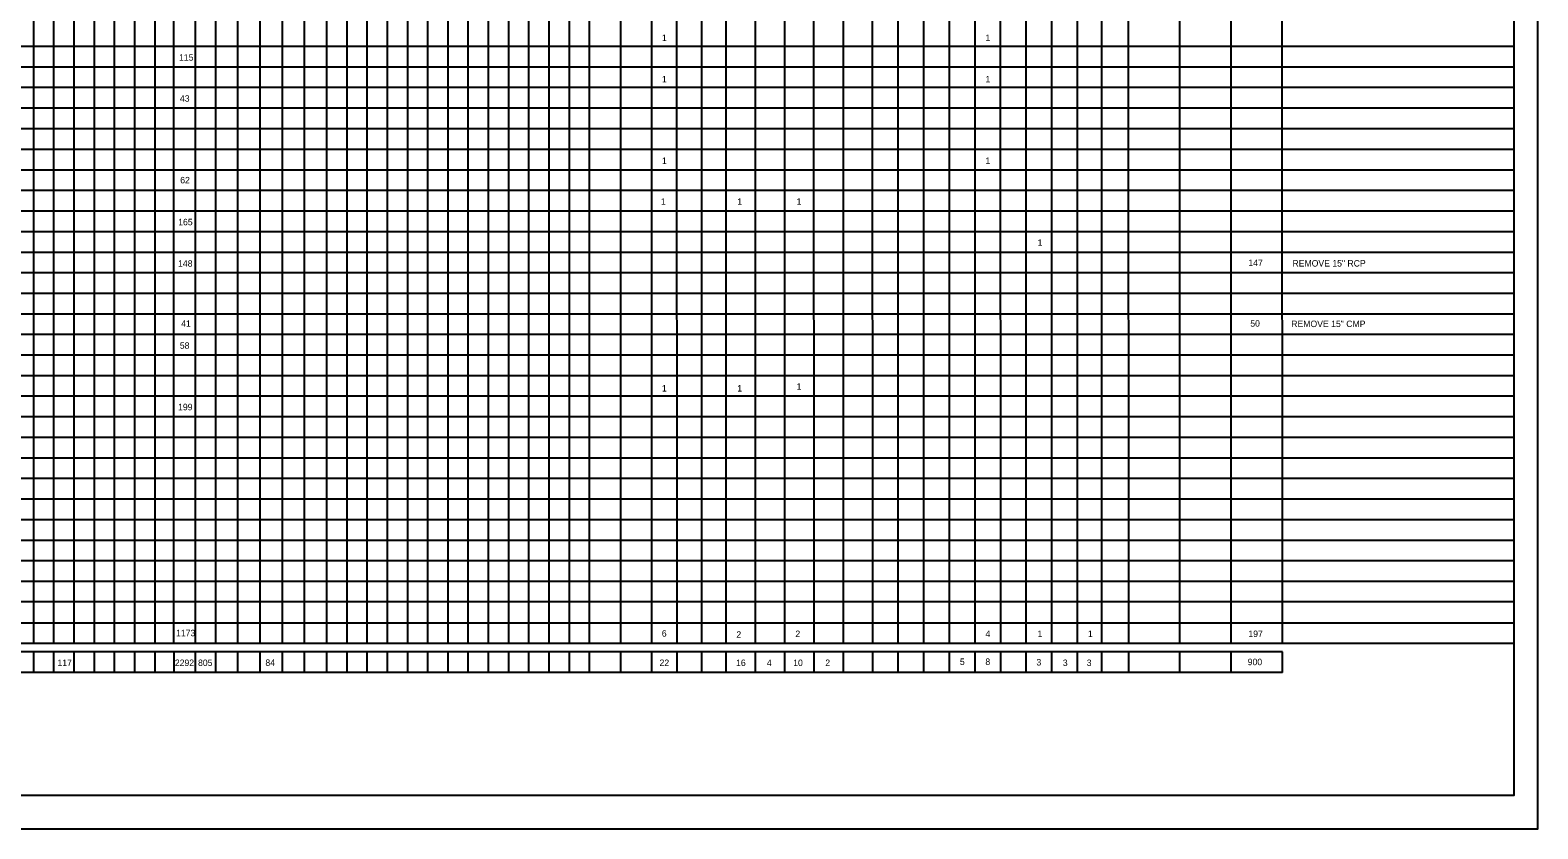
# Model space of a CAD drawing. Extents: x 809447 to 814738, y 647528 to 651206.
# Drawn here: x 813593 to 814712, y 650017 to 650609 of the extents above; entities that cross this region are included whole.
import ezdxf

# ---------------------------------------------------------------- set-up
doc = ezdxf.new("R2010")
doc.units = 0
doc.layers.add('Default', color=7, linetype='Continuous')

msp = doc.modelspace()

# ---------------------------------------------------------------- linework, layer by layer
at = {"layer": 'Default'}
for p, q in [((813595.9, 650154.3), (813595.9, 650925)), ((813699.9, 650154.3), (813699.8, 650925)), ((813813.4, 650154.3), (813813.4, 650925.1)), ((813933.4, 650154.3), (813933.4, 650925.1)), ((813948.4, 650154.3), (813948.4, 650925.1)), ((813963.4, 650154.3), (813963.4, 650925.1)), ((813978.4, 650154.3), (813978.4, 650925.1)), ((813993.4, 650154.3), (813993.4, 650925.1)), ((814008.4, 650154.3), (814008.4, 650925.1)), ((814008.4, 650154.3), (814008.4, 650925.1)), ((814008.4, 650154.3), (814008.4, 650925.1)), ((814054.7, 650154.3), (814054.6, 650925)), ((814109.7, 650154.3), (814109.6, 650925)), ((814109.7, 650154.3), (814109.6, 650925)), ((814131.5, 650154.3), (814131.5, 650925)), ((814218.5, 650154.3), (814218.4, 650925)), ((814256.5, 650154.3), (814256.4, 650925)), ((814275.5, 650154.3), (814275.4, 650925)), ((814294.5, 650154.3), (814294.4, 650925)), ((814313.5, 650154.3), (814313.4, 650925)), ((814332.5, 650154.3), (814332.4, 650925)), ((814351.5, 650154.3), (814351.4, 650925)), ((814370.5, 650154.3), (814370.4, 650925)), ((814388.6, 650154.3), (814388.5, 650925.1)), ((814408.5, 650154.3), (814408.4, 650925)), ((814408.5, 650154.3), (814408.4, 650925)), ((814446.5, 650154.3), (814446.4, 650925)), ((814446.5, 650154.3), (814446.4, 650925)), ((814484.5, 650154.3), (814484.4, 650925)), ((814484.5, 650154.3), (814484.4, 650925)), ((814522.5, 650154.3), (814522.4, 650925)), ((814522.5, 650154.3), (814522.4, 650925)), ((814073.3, 650154.3), (814073.2, 650834.3)), ((814237.5, 650154.3), (814237.4, 650834.3)), ((813610.9, 650154.3), (813610.9, 650817.1)), ((813625.9, 650154.3), (813625.9, 650817.2)), ((813640.9, 650154.3), (813640.9, 650817.1)), ((813655.9, 650154.3), (813655.9, 650817.2)), ((813670.9, 650154.3), (813670.9, 650817.1)), ((813685.9, 650154.3), (813685.9, 650817.2)), ((813715.9, 650154.3), (813715.9, 650817.2)), ((813730.9, 650154.3), (813730.9, 650817.2)), ((813747.4, 650154.3), (813747.4, 650817.2)), ((813763.9, 650154.3), (813763.9, 650817.2)), ((813780.4, 650154.3), (813780.4, 650817.2)), ((813796.9, 650154.3), (813796.9, 650817.2)), ((813813.4, 650154.3), (813813.4, 650817.2)), ((813828.4, 650154.3), (813828.4, 650817.2)), ((813843.4, 650154.3), (813843.4, 650817.2)), ((813858.4, 650154.3), (813858.4, 650817.2)), ((813873.4, 650154.3), (813873.4, 650817.2)), ((813888.4, 650154.3), (813888.4, 650817.2)), ((813903.4, 650154.3), (813903.4, 650817.2)), ((813918.4, 650154.3), (813918.4, 650817.2)), ((813933.4, 650154.3), (813933.4, 650817.2)), ((814091.8, 650154.3), (814091.8, 650811.1)), ((813595.9, 650154.3), (813595.9, 650791.8)), ((814031.6, 650154.3), (814031.5, 650791.8)), ((814153.2, 650154.3), (814153.2, 650749)), ((814175, 650154.3), (814174.9, 650749)), ((814196.7, 650154.3), (814196.7, 650749)), ((814694.6, 650597.3), (813194.6, 650597.3)), ((814694.6, 650582), (813194.6, 650582)), ((814694.6, 650566.7), (813194.6, 650566.7)), ((814694.6, 650551.5), (813194.6, 650551.5)), ((814694.6, 650536.2), (813194.6, 650536.2)), ((814694.6, 650520.9), (813194.6, 650520.9)), ((814694.6, 650505.6), (813194.6, 650505.6)), ((814694.6, 650490.4), (813194.6, 650490.4)), ((814694.6, 650475.1), (813194.6, 650475.1)), ((814694.6, 650459.8), (813194.6, 650459.8)), ((814694.6, 650444.5), (813194.6, 650444.5)), ((814694.6, 650429.3), (813194.6, 650429.3)), ((814694.6, 650414), (813194.6, 650414)), ((814694.6, 650398.8), (813194.6, 650398.8)), ((814694.6, 650383.5), (813194.6, 650383.5)), ((814694.6, 650368.3), (813194.6, 650368.3)), ((814694.6, 650353), (813194.6, 650353)), ((814694.6, 650337.8), (813194.6, 650337.8)), ((814694.6, 650322.5), (813194.6, 650322.5)), ((814694.6, 650307.2), (813194.6, 650307.2)), ((814694.6, 650291.9), (813194.6, 650291.9)), ((814694.6, 650276.7), (813194.6, 650276.7)), ((814694.6, 650261.4), (813194.6, 650261.4)), ((814694.6, 650246.2), (813194.6, 650246.2)), ((814694.6, 650230.9), (813194.6, 650230.9)), ((814694.6, 650215.7), (813194.6, 650215.7)), ((814694.6, 650200.4), (813194.6, 650200.4)), ((814694.6, 650185.2), (813194.6, 650185.2)), ((814694.6, 650169.6), (813194.6, 650169.6)), ((814694.6, 650154.3), (813194.6, 650154.3)), ((814694.6, 650154.3), (813194.6, 650154.3)), ((814522.5, 650148.1), (813415.9, 650148.1)), ((813595.9, 650132.8), (813595.9, 650148.1)), ((813595.9, 650132.8), (813595.9, 650148.1)), ((813610.9, 650132.8), (813610.9, 650148.1)), ((813625.9, 650132.8), (813625.9, 650148.1)), ((813640.9, 650132.8), (813640.9, 650148.1)), ((813655.9, 650132.8), (813655.9, 650148.1)), ((813670.9, 650132.8), (813670.9, 650148.1)), ((813685.9, 650132.8), (813685.9, 650148.1)), ((813700.2, 650132.8), (813700.2, 650148.1)), ((813715.9, 650132.8), (813715.9, 650148.1)), ((813730.9, 650132.8), (813730.9, 650148.1)), ((813747.4, 650132.8), (813747.4, 650148.1)), ((813763.9, 650132.8), (813763.9, 650148.1)), ((813780.4, 650132.8), (813780.4, 650148.1)), ((813796.9, 650132.8), (813796.9, 650148.1)), ((813813.4, 650132.8), (813813.4, 650148.1)), ((813813.4, 650132.8), (813813.4, 650148.1)), ((813828.4, 650132.8), (813828.4, 650148.1)), ((813843.4, 650132.8), (813843.4, 650148.1)), ((813858.4, 650132.8), (813858.4, 650148.1)), ((813873.4, 650132.8), (813873.4, 650148.1)), ((813888.4, 650132.8), (813888.4, 650148.1)), ((813903.4, 650132.8), (813903.4, 650148.1)), ((813918.4, 650132.8), (813918.4, 650148.1)), ((813933.4, 650132.8), (813933.4, 650148.1)), ((813933.4, 650132.8), (813933.4, 650148.1)), ((813948.4, 650132.8), (813948.4, 650148.1)), ((813963.4, 650132.8), (813963.4, 650148.1)), ((813978.4, 650132.8), (813978.4, 650148.1)), ((813993.4, 650132.8), (813993.4, 650148.1)), ((814008.4, 650132.8), (814008.4, 650148.1)), ((814008.4, 650132.8), (814008.4, 650148.1)), ((814008.4, 650132.8), (814008.4, 650148.1)), ((814031.6, 650132.8), (814031.6, 650148.1)), ((814054.7, 650132.8), (814054.7, 650148.1)), ((814073.3, 650132.8), (814073.3, 650148.1)), ((814091.8, 650132.8), (814091.8, 650148.1)), ((814109.7, 650132.8), (814109.7, 650148.1)), ((814109.7, 650132.8), (814109.7, 650148.1)), ((814131.5, 650132.8), (814131.5, 650148.1)), ((814153.2, 650132.8), (814153.2, 650148.1)), ((814175, 650132.8), (814175, 650148.1)), ((814196.7, 650132.8), (814196.7, 650148.1)), ((814218.5, 650132.8), (814218.5, 650148.1)), ((814237.5, 650132.8), (814237.5, 650148.1)), ((814256.5, 650132.8), (814256.5, 650148.1)), ((814275.5, 650132.8), (814275.5, 650148.1)), ((814294.5, 650132.8), (814294.5, 650148.1)), ((814313.5, 650132.8), (814313.5, 650148.1)), ((814332.5, 650132.8), (814332.5, 650148.1)), ((814351.5, 650132.8), (814351.5, 650148.1)), ((814370.5, 650132.8), (814370.5, 650148.1)), ((814388.6, 650132.8), (814388.6, 650148.1)), ((814408.5, 650132.8), (814408.5, 650148.1)), ((814408.5, 650132.8), (814408.5, 650148.1)), ((814446.5, 650132.8), (814446.5, 650148.1)), ((814446.5, 650132.8), (814446.5, 650148.1)), ((814484.5, 650132.8), (814484.5, 650148.1)), ((814484.5, 650132.8), (814484.5, 650148.1)), ((814522.5, 650132.8), (814522.5, 650148.1)), ((814522.5, 650132.8), (814522.5, 650148.1)), ((814522.5, 650132.8), (813415.9, 650132.8))]:
    msp.add_line(p, q, dxfattribs=at)
for points in [[(814712.1, 651116.9), (813028.1, 651116.9), (813028.1, 650016.9), (814712.1, 650016.9)], [(814694.6, 651091.9), (813194.6, 651091.9), (813194.6, 650041.9), (814694.6, 650041.9)]]:
    msp.add_lwpolyline(points, close=True, dxfattribs=at)

# ---------------------------------------------------------------- texts
for s, p in [('1', (814062.1, 650601.3)), ('1', (814302.2, 650601.3)), ('115', (813703.7, 650586.7)), ('1', (814062.1, 650570.6)), ('1', (814302.2, 650570.6)), ('43', (813704.4, 650556.3)), ('1', (814062.1, 650510.1)), ('1', (814302.2, 650510.1)), ('62', (813704.6, 650495.7)), ('1', (814061.3, 650479.8)), ('1', (814118, 650479.8)), ('1', (814162, 650479.8)), ('165', (813703.1, 650464.6)), ('1', (814340.9, 650449.4)), ('148', (813703, 650433.9)), ('147', (814497.3, 650434.4)), ('REMOVE 15" RCP', (814530, 650434)), ('41', (813705.3, 650389.3)), ('50', (814498.7, 650389.4)), ('REMOVE 15" CMP', (814529.1, 650389.1)), ('58', (813704.3, 650373)), ('1', (814062.1, 650341.3)), ('1', (814118, 650341.3)), ('1', (814162, 650342.6)), ('199', (813703, 650327.4)), ('1173', (813701.5, 650159.8)), ('6', (814062, 650159.5)), ('2', (814117.3, 650158.7)), ('2', (814161.1, 650159.2)), ('4', (814302.2, 650159.2)), ('1', (814340.8, 650159.2)), ('1', (814378.2, 650159.2)), ('197', (814497.3, 650159.2)), ('117', (813613.5, 650137.7)), ('2292', (813700.6, 650137.7)), ('805', (813717.8, 650137.7)), ('84', (813767.8, 650137.8)), ('22', (814060.3, 650137.7)), ('16', (814117.1, 650137.7)), ('4', (814140, 650137.7)), ('10', (814159.5, 650137.7)), ('2', (814183.3, 650137.7)), ('5', (814283.2, 650138.5)), ('8', (814302.1, 650138.5)), ('3', (814340, 650138.1)), ('3', (814359.6, 650137.7)), ('3', (814377.3, 650137.7)), ('900', (814496.8, 650138.3))]:
    msp.add_text(s, height=4.8, dxfattribs=at).set_placement(p)

doc.saveas('drawing.dxf')
